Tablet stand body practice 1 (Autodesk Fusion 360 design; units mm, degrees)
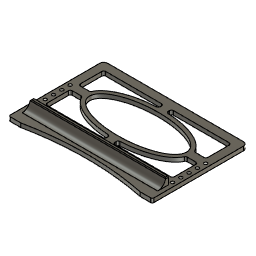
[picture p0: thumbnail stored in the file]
sketch "Sketch1" plane through (0, 0, 0) normal (0, 0, 1) x axis (1, 0, 0)
  line L1 (225.425, 0) -> (0, 0)
  line L2 (225.425, 149.225) -> (225.425, 0)
  line L3 (0, 149.225) -> (225.425, 149.225)
  line L4 (0, 0) -> (0, 149.225)
  point P1 (0, 0)
  point P2 (0, 0)
  point P3 (225.425, 0)
  point P5 (0, 149.225)
  horizontal L1
  vertical L2
  horizontal L3
  vertical L4
  coincident P1 P2
  dimension "d1" distance P2 P3 = 225.425
  dimension "d2" distance P2 P5 = 149.225
extrude "Extrude1" new body sketch "Sketch1" along normal blind 6.35
sketch "Sketch2" plane through (225.425, 0, 0) normal (1, 0, 0) x axis (0, 1, 0)
  line L1 (149.225, 0) -> (0, 0)
  line L2 (149.225, 6.35) -> (149.225, 0)
  line L3 (0, 6.35) -> (149.225, 6.35)
  line L4 (0, 0) -> (0, 6.35)
  line L5 (15.875, 6.35) -> (0, 6.35)
  line L6 (28.575, 6.35) -> (15.875, 6.35)
  line L7 (28.575, 17.907) -> (28.575, 6.35)
  line L8 (31.75, 17.907) -> (28.575, 17.907)
  line L9 (31.75, 6.35) -> (31.75, 17.907)
  line L10 (28.575, 6.35) -> (31.75, 6.35)
  line L11 (27.305, 6.35) -> (28.575, 6.35)
  line L12 (27.305, 16.637) -> (27.305, 6.35)
  line L13 (27.305, 16.637) -> (28.575, 17.907)
  line L14 (34.0111, 17.907) -> (28.575, 17.907)
  point P5 (0, 6.35)
  point P6 (0, 6.35)
  point P11 (31.75, 6.35)
  point P7 (15.875, 6.35)
  point P8 (28.575, 6.35)
  point P9 (28.575, 17.907)
  point P10 (31.75, 17.907)
  point P12 (27.305, 6.35)
  coincident P5 P6
  perpendicular L4 L5
  parallel L3 L6
  perpendicular L6 L7
  perpendicular L7 L8
  coincident L3 P11
  perpendicular L3 L9
  perpendicular L7 L11
  perpendicular L6 L12
  horizontal L14
  dimension "d5" distance P6 P7 = 15.875
  dimension "d6" distance P7 P8 = 12.7
  dimension "d8" distance P8 P9 = 11.557
  dimension "d9" distance P9 P10 = 3.175
  dimension "d10" distance P8 P12 = 1.27
  dimension "d11" angle L13 L14 = 135
extrude "Extrude2" add sketch "Sketch2" profile of L3 L6 L7 L8 L9 L10 L11 L12 L13 against normal blind 225.425
fillet "Fillet1" radius 12.7
sketch "Sketch3" plane through (0, 0, 6.35) normal (0, 0, 1) x axis (-1, 0, 0)
  line L1 (0, -14.8363) -> (-225.425, -14.8363)
  line L2 (0, 0) -> (0, -14.8363)
  line L3 (-225.425, 0) -> (0, 0)
  line L4 (-225.425, -14.8363) -> (-225.425, 0)
  line L5 (-19.05, 0) -> (0, 0)
  line L6 (-206.375, 0) -> (-225.425, 0)
  line L7 (-206.375, 0) -> (-19.05, 0)
  arc A1 centre (-112.7125, 457.2) radius 466.6953 clockwise from (-19.05, 0) to (-206.375, 0)
  point P4 (0, 0)
  point P6 (0, 0)
  point P5 (-225.425, 0)
  point P8 (-225.425, 0)
  point P7 (-19.05, 0)
  point P9 (-206.375, 0)
  point P10 (-112.7125, 457.2)
  coincident P4 P6
  perpendicular L2 L5
  coincident P5 P8
  perpendicular L4 L6
  dimension "d16" distance P6 P7 = 19.05
  dimension "d17" distance P8 P9 = 19.05
  dimension "d18" distance L3 P10 = 457.2
extrude "Extrude3" cut sketch "Sketch3" profile of L3 A1 L7 against normal blind 6.35
sketch "Sketch4" plane through (0, 0, 17.907) normal (0, 0, 1) x axis (-1, 0, 0)
  line L1 (-225.425, -31.75) -> (-225.425, -28.575)
  line L2 (0, -31.75) -> (-225.425, -31.75)
  line L3 (0, -28.575) -> (0, -31.75)
  line L4 (-225.425, -28.575) -> (0, -28.575)
  line L5 (-6.35, -31.75) -> (0, -31.75)
  line L6 (-6.35, -12.7) -> (-6.35, -31.75)
  line L7 (0, -12.7) -> (-6.35, -12.7)
  line L8 (0, -31.75) -> (0, -12.7)
  point P4 (0, -31.75)
  point P6 (0, -31.75)
  point P7 (-6.35, -31.75)
  point P9 (0, -12.7)
  horizontal L5
  vertical L6
  horizontal L7
  vertical L8
  coincident P4 P6
  dimension "d21" distance P6 P7 = 6.35
  dimension "d22" distance P6 P9 = 19.05
work_plane "WorkPlane1"
extrude "Extrude4" cut sketch "Sketch4" profile of L2 L3 L4 L5 L6 L7 L8 to an object
sketch "Sketch5" plane through (0, 0, 17.907) normal (0, 0, 1) x axis (-1, 0, 0)
  line L1 (-6.35, -28.575) -> (-6.35, -31.75)
  line L2 (-225.425, -28.575) -> (-6.35, -28.575)
  line L3 (-225.425, -31.75) -> (-225.425, -28.575)
  line L4 (-6.35, -31.75) -> (-225.425, -31.75)
  line L5 (-219.075, -31.75) -> (-225.425, -31.75)
  line L6 (-219.075, -12.7) -> (-219.075, -31.75)
  line L7 (-225.425, -12.7) -> (-219.075, -12.7)
  line L8 (-225.425, -31.75) -> (-225.425, -12.7)
  point P5 (-225.425, -31.75)
  point P6 (-225.425, -31.75)
  point P7 (-219.075, -31.75)
  point P9 (-225.425, -12.7)
  horizontal L5
  vertical L6
  horizontal L7
  vertical L8
  coincident P5 P6
  dimension "d25" distance P6 P7 = 6.35
  dimension "d26" distance P6 P9 = 19.05
extrude "Extrude5" cut sketch "Sketch5" profile of L2 L3 L4 L5 L6 L7 L8 to an object
chamfer "Chamfer1" distance 1.27
sketch "Sketch6" plane through (0, 0, 6.35) normal (0, 0, 1) x axis (-1, 0, 0)
  line L1 (-225.425, -149.225) -> (-225.425, 0)
  line L2 (0, -149.225) -> (-225.425, -149.225)
  line L3 (0, 0) -> (0, -149.225)
  line L4 (-19.05, 0) -> (0, 0)
  line L5 (-225.425, 0) -> (-206.375, 0)
  line L6 (-219.075, -14.8363) -> (-219.075, -31.75)
  line L7 (-6.35, -14.8363) -> (-219.075, -14.8363)
  line L8 (-6.35, -31.75) -> (-6.35, -14.8363)
  line L9 (-219.075, -31.75) -> (-6.35, -31.75)
  line L10 (-112.7125, -31.75) -> (-112.7125, -149.225)
  line L11 (-225.425, -90.4875) -> (-112.7125, -90.4875)
  curve K1 (-188.9125, -90.4875) -> (-36.5125, -90.4875)
  curve K2 (-112.7125, -122.2375) -> (-112.7125, -58.7375)
  arc A1 centre (-112.7125, 457.2) radius 466.6953 clockwise from (-19.05, 0) to (-206.375, 0)
  closed curve K3 centre (-112.7125, -90.4875)
  point P13 (-112.7125, -149.225)
  point P14 (-112.7125, -31.75)
  point P15 (-112.7125, -90.4875)
  point P18 (-36.5125, -90.4875)
  point P19 (-188.9125, -90.4875)
  point P20 (-112.7125, -58.7375)
  point P21 (-112.7125, -122.2375)
  point P17 (-112.7125, -90.4875)
  point P16 (-225.425, -90.4875)
  midpoint L2 P13
  midpoint L9 P14
  midpoint L10 P15
  perpendicular L10 L11
  coincident K3 P18
  coincident K3 P19
  coincident K3 P20
  coincident K3 P21
  coincident P15 P17
  perpendicular L10 K1
  coincident L1 P16
  dimension "d37" distance K3 = 152.4
  dimension "d38" = 31.75
extrude "Extrude6" cut sketch "Sketch6" profile of L10 L11 K3 no distance stored
sketch "Sketch7" plane through (0, 0, 6.35) normal (0, 0, 1) x axis (-1, 0, 0)
  line L1 (-212.725, -136.525) -> (-12.7, -136.525)
  line L2 (-212.725, -44.45) -> (-212.725, -136.525)
  line L3 (-12.7, -44.45) -> (-212.725, -44.45)
  line L4 (-12.7, -136.525) -> (-12.7, -44.45)
  line L5 (-225.425, -149.225) -> (-225.425, 0)
  line L6 (0, -149.225) -> (-225.425, -149.225)
  line L7 (0, 0) -> (0, -149.225)
  line L8 (-19.05, 0) -> (0, 0)
  line L9 (-225.425, 0) -> (-206.375, 0)
  line L10 (-219.075, -14.8363) -> (-219.075, -31.75)
  line L11 (-6.35, -14.8363) -> (-219.075, -14.8363)
  line L12 (-6.35, -31.75) -> (-6.35, -14.8363)
  line L13 (-219.075, -31.75) -> (-6.35, -31.75)
  line L14 (-106.3625, -90.4875) -> (-112.7125, -90.4875)
  line L15 (-112.7125, -44.45) -> (-112.7125, -90.4875)
  line L16 (-112.7125, -136.525) -> (-112.7125, -90.4875)
  line L17 (-106.3625, -84.1375) -> (-106.3625, -90.4875)
  line L18 (-106.3625, -44.45) -> (-106.3625, -52.5004)
  line L19 (-119.0625, -84.1375) -> (-119.0625, -90.4875)
  line L20 (-119.0625, -44.45) -> (-119.0625, -52.5004)
  line L21 (-106.3625, -122.1271) -> (-106.3625, -90.4875)
  line L22 (-106.3625, -136.525) -> (-106.3625, -128.4746)
  line L23 (-119.0625, -122.1271) -> (-119.0625, -90.4875)
  line L24 (-119.0625, -136.525) -> (-119.0625, -128.4746)
  line L25 (-119.0625, -84.1375) -> (-112.7125, -84.1375)
  line L26 (-212.725, -84.1375) -> (-194.1079, -84.1375)
  line L27 (-119.0625, -96.8375) -> (-112.7125, -96.8375)
  line L28 (-212.725, -96.8375) -> (-194.1079, -96.8375)
  line L29 (-119.0625, -90.4875) -> (-112.7125, -90.4875)
  line L30 (-195.2625, -90.4875) -> (-188.9125, -90.4875)
  line L31 (-38.0521, -84.1375) -> (-112.7125, -84.1375)
  line L32 (-12.7, -84.1375) -> (-31.3171, -84.1375)
  line L33 (-38.0521, -96.8375) -> (-112.7125, -96.8375)
  line L34 (-12.7, -96.8375) -> (-31.3171, -96.8375)
  closed curve K1 centre (-112.7125, -90.4875)
  arc A1 centre (-112.7125, 457.2) radius 466.6953 clockwise from (-19.05, 0) to (-206.375, 0)
  closed curve K2 centre (-112.7125, -90.4875)
  closed curve K3 centre (-112.7125, -90.4875)
  point P6 (-112.7125, -90.4875)
  point P20 (-112.7125, -90.4875)
  point P18 (-112.7125, -90.4875)
  point P21 (-112.7125, -90.4875)
  point P22 (-112.7125, -44.45)
  point P23 (-112.7125, -90.4875)
  point P24 (-112.7125, -136.525)
  point P39 (-106.3625, -84.1375)
  point P41 (-119.0625, -52.5004)
  point P42 (-106.3625, -52.5004)
  point P43 (-106.3625, -122.1271)
  point P44 (-106.3625, -128.4746)
  point P45 (-119.0625, -122.1271)
  point P46 (-119.0625, -128.4746)
  point P47 (-119.0625, -96.8375)
  point P48 (-194.1079, -96.8375)
  point P49 (-194.1079, -84.1375)
  point P50 (-188.9125, -90.4875)
  point P51 (-195.2625, -90.4875)
  point P52 (-38.0521, -84.1375)
  point P53 (-31.3171, -84.1375)
  point P54 (-38.0521, -96.8375)
  point P55 (-31.3171, -96.8375)
  horizontal L1
  vertical L2
  horizontal L3
  vertical L4
  coincident P6 P20
  perpendicular L2 L29
  coincident P18 P21
  midpoint L3 P22
  perpendicular L3 L15
  coincident P18 P23
  midpoint L1 P24
  coincident P39 L31
  collinear L17 L18
  collinear L19 L20
  coincident K3 P41
  coincident K3 P42
  coincident K1 P43
  coincident K3 P44
  collinear L21 L22
  coincident K1 P45
  coincident K3 P46
  collinear L23 L24
  collinear L25 L26
  coincident L23 P47
  collinear L27 L28
  coincident K3 P48
  coincident K3 P49
  coincident K1 P50
  collinear L29 L30
  coincident K3 P51
  coincident K1 P52
  coincident K3 P53
  collinear L31 L32
  coincident K1 P54
  coincident K3 P55
  collinear L33 L34
  dimension "d65" distance L1 L6 = 12.7
  dimension "d66" distance L2 L5 = 12.7 (= "d65")
  dimension "d67" distance L3 L13 = 12.7
  dimension "d68" = 38.1
extrude "Extrude7" cut sketch "Sketch7" profile of L1 L2 L3 L4 K3 L24 L22 L26 L32 L28 L34 L18 L20 no distance stored
fillet "Fillet2" radius 3
fillet "Fillet3" radius 3
hole "Hole1" HoleDepth 35.56 HoleDiameter 5.035 TipAngle 118 RefDim1 6.35 RefDim2 38.1
rectangular_pattern "R-Pattern1" uSpaceDistance -52.07 vSpaceDistance 212.725
fillet "Fillet4" radius 6
fillet "Fillet5" radius 2.5
fillet "Fillet6" radius 2.5
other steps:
thread "Thread1"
